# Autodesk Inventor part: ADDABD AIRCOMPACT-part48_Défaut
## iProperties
Shininess: 64.0
Length Units: 11269
Angle Units: 11279
Time Units: 11290
Mass Units: 11283
Length Display Precision: 3
Angle Display Precision: 2
Compacted: True
Part Number: ADDABD AIRCOMPACT-part48_Défaut
Document SubType Name: Modeling
Created: 2006-01
Material: Par défaut
Designer: riri
Density: 0.0
Volumn: 0.0
Area: 0.0
PropertySet Name: Model Information
Control State: 0
Master: False
Checked Out: False
Author: riri
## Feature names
1. Base1
